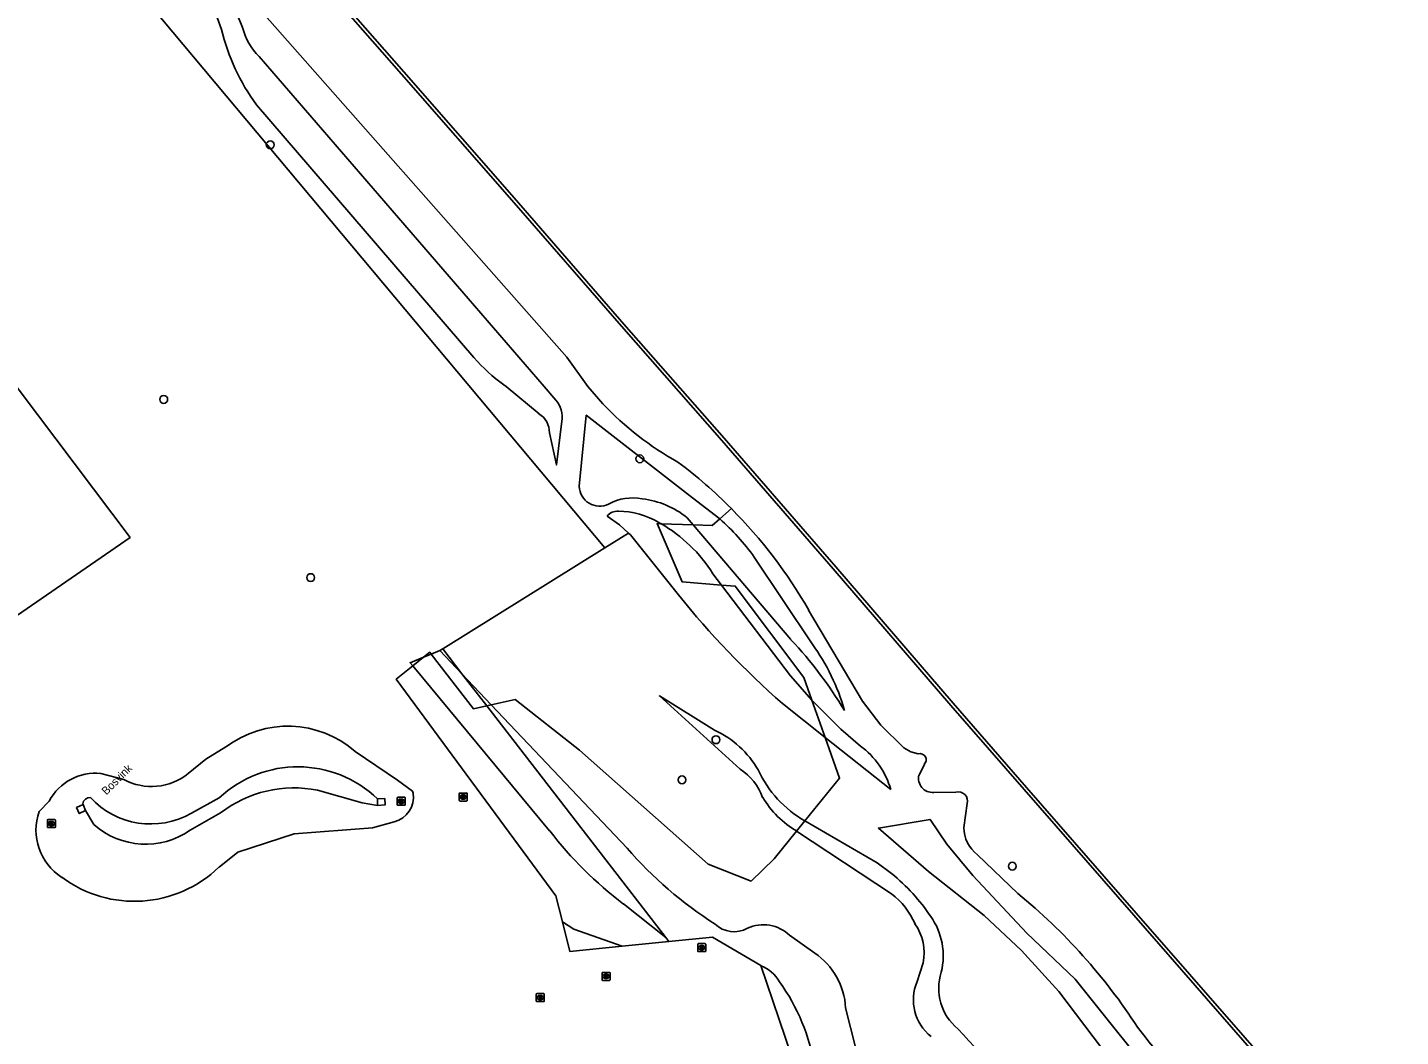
# Model space of a CAD drawing. Extents: x 156664 to 157568, y 383571 to 384421.
# Drawn here: x 157142.1 to 157313.7, y 383918.8 to 384044.9 of the extents above; entities that cross this region are included whole.
import ezdxf

# ---------------------------------------------------------------- set-up
doc = ezdxf.new("R2010")
doc.units = 0
for name, color, linetype in [('IMGEO_Boom', 7, 'Continuous'), ('IMGEO_Gemengd_bos', 7, 'Continuous'), ('IMGEO_Greppel_droge_sloot', 7, 'Continuous'), ('IMGEO_Groenvoorziening', 7, 'Continuous'), ('IMGEO_Hek', 7, 'Continuous'), ('IMGEO_Houtwal', 7, 'Continuous'), ('IMGEO_Kademuur', 7, 'Continuous'), ('IMGEO_Kolk', 7, 'Continuous'), ('IMGEO_Loofbos', 7, 'Continuous'), ('IMGEO_Openbare_ruimte_label', 7, 'Continuous'), ('IMGEO_Rioolput', 7, 'Continuous'), ('IMGEO_Terreindeel_gesloten', 7, 'Continuous')]:
    doc.layers.add(name, color=color, linetype=linetype)

msp = doc.modelspace()

# ---------------------------------------------------------------- linework, layer by layer
at = {"layer": 'IMGEO_Boom'}
for centre in [(157172.48, 384030.23), (157159.17, 383998.4), (157218.67, 383990.98), (157177.53, 383976.13), (157228.18, 383955.86), (157223.94, 383950.85), (157265.22, 383940.05)]:
    msp.add_circle(centre, 0.489, dxfattribs=at)
at = {"layer": 'IMGEO_Gemengd_bos'}
for points in [[(157228.65, 383983.48), (157230.11, 383984.75)], [(157221.29, 383982.87), (157225.32, 383982.73)], [(157239.77, 383972.07), (157246.51, 383960.69), (157248.79, 383957.68), (157251.67, 383954.83), (157252.53, 383954.36), (157253.47, 383954.09)], [(157238.27, 383944.43), (157235.47, 383940.96), (157232.58, 383938.19), (157227.2, 383940.31), (157211.14, 383954.54), (157203.08, 383960.87), (157200.11, 383960.22)], [(157228.01, 383957.05), (157221.12, 383961.34), (157231.2, 383952.19)], [(157240.17, 383960.81), (157243.8, 383957.17), (157246.25, 383955.07)], [(157200.11, 383960.22), (157199.53, 383960.09)], [(157200.11, 383960.22), (157217.09, 383942.31)], [(157239.3, 383945.71), (157243.63, 383951.07), (157241.83, 383956.14)], [(157250.03, 383949.63), (157241.83, 383956.14)], [(157254.23, 383952.79), (157253.56, 383951.45)], [(157255.41, 383949.28), (157258.18, 383949.3)], [(157259.59, 383947.9), (157259.15, 383944.9)], [(157239.3, 383945.71), (157238.27, 383944.43)], [(157250.14, 383939.13), (157248.32, 383940.46), (157239.3, 383945.71)], [(157303.47, 383891.7), (157300.02, 383895.94), (157297.8, 383897.29), (157289.36, 383906.54), (157284.6, 383911.52), (157273.07, 383925.95), (157267.04, 383931.67), (157260.3, 383938.88), (157257.03, 383942.79), (157254.94, 383945.91), (157248.49, 383944.82), (157254.75, 383939.38), (157261.69, 383933.87), (157266.36, 383929.5), (157271.02, 383924.41), (157276.36, 383917.34), (157282.3, 383910.19), (157297.68, 383894.11), (157299.46, 383892.07), (157301.69, 383888.84), (157300.48, 383888.07), (157303.25, 383884.02)], [(157250.13, 383936.61), (157238.27, 383944.43)], [(157260.86, 383941.47), (157265.93, 383936.62)], [(157222.29, 383930.64), (157227.77, 383931.19), (157233.78, 383927.62)], [(157237.39, 383931.42), (157240.53, 383929.17)], [(157253.32, 383925.62), (157254.09, 383927.96)], [(157244.39, 383922.35), (157245.62, 383917.45)]]:
    msp.add_lwpolyline(points, dxfattribs=at)
for centre, radius, start, end in [((157186.72, 383941.66), 61.15, 29.8152, 44.7984), ((157222.96, 383946.06), 12.1, 29.8538, 65.3154), ((157240.04, 383946.72), 10.41, 16.2761, 53.3333), ((157253.69, 383953.35), 0.772, 313.8246, 106.7158), ((157227.4, 383946.25), 7.04, 19.8803, 57.4196), ((157246.5, 383958.18), 14.4, 205.0583, 240.022), ((157255.24, 383951.01), 1.74, 165.4769, 275.4287), ((157244.62, 383955.06), 12.38, 211.1926, 239.1594), ((157258.49, 383948.2), 1.14, 344.5925, 106.0172), ((157263.58, 383944.97), 4.43, 180.8714, 232.1785), ((157254.93, 383975.03), 50.03, 220.8459, 237.5294), ((157235.24, 383920.64), 23.74, 33.5708, 51.1424), ((157243.79, 383928.62), 10.2, 24.5965, 51.576), ((157219.84, 383880.31), 72.77, 32.9958, 50.7037), ((157230.44, 383935.23), 3.37, 225.5364, 299.7246), ((157247.8, 383929.21), 6.4, 348.7541, 34.8077), ((157248, 383928.83), 8.59, 346.3576, 35.1112), ((157234.1, 383927.95), 4.78, 46.4665, 114.5596), ((157235.58, 383921.87), 8.82, 3.1419, 55.8635), ((157232.08, 383923.27), 4.67, 30.02, 68.5963), ((157262.53, 383924.79), 6.51, 161.9515, 230.875), ((157216.14, 383911.15), 24.66, 8.9825, 35.887), ((157258.75, 383923.35), 5.89, 157.3225, 231.3189), ((157303.08, 383959.04), 59.49, 221.3471, 237.1641), ((157379.75, 383994.77), 124, 217.1164, 228.5496)]:
    msp.add_arc(centre, radius, start, end, dxfattribs=at)
at = {"layer": 'IMGEO_Greppel_droge_sloot'}
for points in [[(157166.11, 383948.59), (157162.63, 383946.67)], [(157178.39, 383949.54), (157183.98, 383947.96), (157185.9, 383947.65), (157185.9, 383947.66)], [(157185.9, 383947.66), (157185.9, 383948.46)], [(157149.06, 383947.84), (157149.09, 383947.75)], [(157149.09, 383947.75), (157149.41, 383947.01)], [(157149.41, 383947.01), (157150.45, 383945.26)], [(157162.48, 383944.55), (157166.28, 383946.71)]]:
    msp.add_lwpolyline(points, dxfattribs=at)
for centre, radius, start, end in [((157175.93, 383938.12), 14.36, 46.057, 133.1961), ((157149.96, 383947.72), 0.913, 87.0362, 172.8465), ((157157.55, 383955.59), 10.26, 222.6552, 299.6813), ((157175.41, 383934.98), 14.86, 78.4476, 127.8989), ((157156.91, 383952.49), 9.69, 228.1896, 305.0149)]:
    msp.add_arc(centre, radius, start, end, dxfattribs=at)
at = {"layer": 'IMGEO_Groenvoorziening'}
for points in [[(157095.74, 384121.39), (157214.31, 383979.84)], [(157047.52, 384049.68), (157048.49, 384046.4), (157118.08, 383955.71), (157154.96, 383981.15), (157087.62, 384070.54), (157084.35, 384074.37)], [(157214.31, 383979.84), (157217.27, 383981.69)], [(157214.31, 383979.84), (157194.04, 383967.21)], [(157194.04, 383967.21), (157193.69, 383967)], [(157194.04, 383967.21), (157196.44, 383964.1)], [(157191.63, 383966.17), (157189.95, 383965.49), (157190.29, 383965.09)], [(157192.61, 383966.56), (157192.42, 383966.8), (157191.63, 383966.17)], [(157200.11, 383960.22), (157196.44, 383964.1)], [(157166.95, 383954.96), (157164.45, 383953.44), (157162.24, 383951.62)], [(157190.25, 383949.45), (157188.39, 383950.82), (157183.1, 383954.38)], [(157154.17, 383950.88), (157151.32, 383951.62)], [(157190.36, 383949.17), (157190.25, 383949.45)], [(157144.87, 383948.19), (157143.6, 383946.88)], [(157166.08, 383939.94), (157168.41, 383941.82), (157175.48, 383944.08), (157185.25, 383944.83), (157187.96, 383945.61)], [(157233.78, 383927.62), (157237.6, 383916.48), (157235.41, 383912.05)]]:
    msp.add_lwpolyline(points, dxfattribs=at)
for centre, radius, start, end in [((157174.67, 383944.78), 12.78, 48.7114, 127.1896), ((157150.62, 383945.16), 6.51, 83.8156, 152.216), ((157157.64, 383957.39), 7.37, 241.9236, 308.5702), ((157187.14, 383948.75), 3.25, 284.7009, 7.3932), ((157150.18, 383944.56), 6.98, 160.637, 237.6994), ((157155.51, 383950.82), 15.16, 233.2939, 314.1575)]:
    msp.add_arc(centre, radius, start, end, dxfattribs=at)
at = {"layer": 'IMGEO_Hek'}
for points in [[(157194.04, 383967.21), (157196.44, 383964.1)], [(157196.44, 383964.1), (157199.53, 383960.09)], [(157199.53, 383960.09), (157221.91, 383931.13)]]:
    msp.add_lwpolyline(points, dxfattribs=at)
at = {"layer": 'IMGEO_Houtwal'}
msp.add_lwpolyline([(157168.33, 384050.41), (157209.55, 384003.67), (157212.18, 384000), (157214.05, 383997.86)], dxfattribs=at)
for centre, radius, start, end in [((157242.19, 384024.36), 38.65, 223.2743, 240.9715), ((157186.7, 383941.66), 61.17, 44.7943, 53.0885)]:
    msp.add_arc(centre, radius, start, end, dxfattribs=at)
at = {"layer": 'IMGEO_Kademuur'}
for points in [[(157139.95, 384094.76), (157138.9, 384095.94), (157138.92, 384096.14), (157139.23, 384096.4), (157144.99, 384089.82), (157158.9, 384073.9), (157171.41, 384059.63), (157179.52, 384050.39), (157189.18, 384039.33), (157202.96, 384023.58), (157216.69, 384007.81), (157229.23, 383993.54), (157243.16, 383977.49), (157257.85, 383960.42), (157267.01, 383949.91), (157280.72, 383934.19), (157294.31, 383918.59), (157307.06, 383903.94), (157311.27, 383899.09), (157313.54, 383896.26), (157313.74, 383894.72)], [(157142.02, 384092.64), (157144.69, 384089.56), (157158.6, 384073.63), (157171.11, 384059.37), (157179.22, 384050.12), (157188.88, 384039.06), (157202.66, 384023.32), (157216.39, 384007.55), (157228.93, 383993.27), (157242.85, 383977.23), (157257.55, 383960.15), (157266.71, 383949.64), (157280.42, 383933.92), (157294.01, 383918.32), (157306.76, 383903.67), (157310.96, 383898.84), (157313.16, 383896.1), (157313.34, 383894.66), (157313.74, 383894.72)]]:
    msp.add_lwpolyline(points, dxfattribs=at)
at = {"layer": 'IMGEO_Kolk'}
for p, q in [((157188.35, 383947.75), (157188.35, 383948.6)), ((157188.43, 383948.67), (157189.28, 383948.67)), ((157188.84, 383948.45), (157188.87, 383948.45)), ((157189.36, 383948.6), (157189.36, 383947.75)), ((157189.28, 383947.67), (157188.43, 383947.67)), ((157188.86, 383947.89), (157188.84, 383947.89)), ((157144.63, 383944.95), (157144.63, 383945.81)), ((157144.7, 383945.88), (157145.56, 383945.88)), ((157145.56, 383944.88), (157144.7, 383944.88)), ((157145.14, 383945.1), (157145.11, 383945.1)), ((157145.12, 383945.66), (157145.14, 383945.66)), ((157145.63, 383945.81), (157145.63, 383944.95))]:
    msp.add_line(p, q, dxfattribs=at)
for points in [[(157188.35, 383947.75), (157188.35, 383948.6)], [(157188.43, 383948.67), (157189.28, 383948.67)], [(157188.67, 383948.37), (157188.8, 383948.37), (157188.8, 383948.22), (157188.93, 383948.37), (157189.09, 383948.37), (157188.95, 383948.22), (157189.1, 383947.97), (157188.95, 383947.97), (157188.86, 383948.14), (157188.8, 383948.07), (157188.8, 383947.97), (157188.67, 383947.97), (157188.67, 383948.37)], [(157189.36, 383948.6), (157189.36, 383947.75)], [(157189.28, 383947.67), (157188.43, 383947.67)], [(157144.63, 383944.95), (157144.63, 383945.81)], [(157144.7, 383945.88), (157145.56, 383945.88)], [(157145.56, 383944.88), (157144.7, 383944.88)], [(157144.95, 383945.58), (157145.07, 383945.58), (157145.07, 383945.43), (157145.2, 383945.58), (157145.37, 383945.58), (157145.22, 383945.43), (157145.37, 383945.18), (157145.22, 383945.18), (157145.14, 383945.34), (157145.07, 383945.28), (157145.07, 383945.18), (157144.95, 383945.18), (157144.95, 383945.58)], [(157145.63, 383945.81), (157145.63, 383944.95)]]:
    msp.add_lwpolyline(points, dxfattribs=at)
for centre, start, end in [((157188.43, 383948.6), 91.552, 178.448), ((157188.43, 383948.6), 91.552, 178.448), ((157189.28, 383948.6), 1.552, 88.448), ((157189.28, 383948.6), 1.552, 88.448), ((157188.43, 383947.75), 181.552, 268.448), ((157188.43, 383947.75), 181.552, 268.448), ((157189.28, 383947.75), 271.552, 358.448), ((157189.28, 383947.75), 271.552, 358.448), ((157144.71, 383945.8), 91.552, 178.448), ((157144.71, 383945.8), 91.552, 178.448), ((157144.71, 383944.96), 181.552, 268.448), ((157144.71, 383944.96), 181.552, 268.448), ((157145.55, 383945.8), 1.552, 88.448), ((157145.55, 383945.8), 1.552, 88.448), ((157145.55, 383944.96), 271.552, 358.448), ((157145.55, 383944.96), 271.552, 358.448)]:
    msp.add_arc(centre, 0.0765, start, end, dxfattribs=at)
for centre, major_axis, ratio, start_param, end_param in [((157188.84, 383948.17), (-0.387, 0.002), 0.722429, 4.712389, 7.853982), ((157188.87, 383948.17), (-0.39, 0.002), 0.717154, 1.570796, 4.712389), ((157145.12, 383945.38), (-0.387, 0.002), 0.722429, 4.712389, 7.853982), ((157145.14, 383945.38), (-0.39, 0.002), 0.717154, 1.570796, 4.712389)]:
    msp.add_ellipse(centre, major_axis=major_axis, ratio=ratio, start_param=start_param, end_param=end_param, dxfattribs=at)
at = {"layer": 'IMGEO_Loofbos'}
for points in [[(157165.83, 384046.13), (157166.38, 384044.65)], [(157207.93, 383998.59), (157206.71, 384000), (157171.09, 384041.26)], [(157170.76, 384035.22), (157197.94, 384003.63)], [(157201.69, 384000.22), (157201.95, 384000), (157206.07, 383996.62)], [(157228.65, 383983.48), (157225.25, 383986.11), (157211.98, 383996.42), (157211.09, 383987.54)], [(157207.38, 383994.23), (157208.25, 383990.21), (157208.98, 383996.03)], [(157217.27, 383981.69), (157216.11, 383982.74), (157214.58, 383983.82)], [(157221.29, 383982.87), (157220.82, 383982.89), (157223.95, 383975.6), (157228.87, 383975.2)], [(157221.05, 383983.01), (157221.29, 383982.87)], [(157224.58, 383983.6), (157225.32, 383982.73)], [(157228.65, 383983.48), (157227.69, 383982.65), (157225.32, 383982.73)], [(157225.32, 383982.73), (157237.55, 383968.37)], [(157223.51, 383973.96), (157217.49, 383981.49), (157217.27, 383981.69)], [(157240.19, 383967.83), (157232.97, 383978.7)], [(157228.87, 383975.2), (157227.81, 383976.61)], [(157240.17, 383960.81), (157239.17, 383963.64), (157230.59, 383975.07), (157228.87, 383975.2)], [(157228.87, 383975.2), (157237.49, 383963.85), (157240.17, 383960.81)], [(157191.63, 383966.17), (157190.29, 383965.09)], [(157192.61, 383966.56), (157191.63, 383966.17)], [(157193.69, 383967), (157192.61, 383966.56)], [(157199.53, 383960.09), (157197.87, 383959.73), (157192.61, 383966.56)], [(157196.44, 383964.1), (157193.69, 383967)], [(157190.29, 383965.09), (157188.23, 383963.43), (157208.19, 383936.36), (157209, 383933.11)], [(157190.29, 383965.09), (157207.4, 383944.48)], [(157199.53, 383960.09), (157196.44, 383964.1)], [(157241.83, 383956.14), (157236.51, 383960.37)], [(157240.17, 383960.81), (157241.83, 383956.14)], [(157221.91, 383931.13), (157199.53, 383960.09)], [(157216.63, 383935.33), (157221.91, 383931.13)], [(157209, 383933.11), (157210.42, 383932.17), (157216.46, 383930.05)], [(157209, 383933.11), (157209.92, 383929.4), (157216.46, 383930.05)], [(157222.29, 383930.64), (157221.91, 383931.13)], [(157216.46, 383930.05), (157222.29, 383930.64)]]:
    msp.add_lwpolyline(points, dxfattribs=at)
for centre, radius, start, end in [((157156.36, 384040.05), 13.56, 20.9435, 42.8742), ((157192.46, 384051.03), 26.85, 193.7387, 216.0861), ((157176.35, 384046.65), 7.53, 193.471, 225.7471), ((157215.25, 384018.85), 23.05, 221.3169, 233.9441), ((157205.64, 383996.15), 3.34, 357.8266, 46.8798), ((157204.65, 383994.29), 2.72, 358.6994, 58.7896), ((157213.66, 383987.63), 2.57, 182.2171, 295.5259), ((157217.73, 383980.04), 6.05, 78.1031, 119.3361), ((157215.86, 383982.77), 1.66, 85.5723, 140.7857), ((157215.89, 383974.32), 10.11, 59.3082, 89.4451), ((157217.78, 383975.27), 10.76, 50.7584, 83.5989), ((157212.06, 383966.75), 18.58, 32.052, 60.2073), ((157209.01, 383961.38), 29.56, 35.8481, 48.3681), ((157307.01, 384040.88), 107.01, 218.71, 228.7903), ((157199.79, 383932.87), 51.83, 30.923, 43.2254), ((157219.38, 383952.53), 25.83, 15.6766, 36.3184), ((157246.48, 383974.68), 49.39, 217.703, 232.8268)]:
    msp.add_arc(centre, radius, start, end, dxfattribs=at)
at = {"layer": 'IMGEO_Rioolput'}
for p, q in [((157196.09, 383948.28), (157196.09, 383949.13)), ((157196.17, 383949.2), (157197.02, 383949.2)), ((157196.58, 383948.98), (157196.61, 383948.98)), ((157196.6, 383948.42), (157196.58, 383948.42)), ((157197.09, 383949.13), (157197.09, 383948.28)), ((157197.02, 383948.2), (157196.17, 383948.2)), ((157225.9, 383929.44), (157225.9, 383930.29)), ((157225.98, 383930.37), (157226.83, 383930.37)), ((157226.83, 383929.37), (157225.98, 383929.37)), ((157226.39, 383930.15), (157226.42, 383930.15)), ((157226.41, 383929.59), (157226.39, 383929.59)), ((157226.9, 383930.29), (157226.9, 383929.44)), ((157213.95, 383925.85), (157213.95, 383926.7)), ((157214.03, 383926.78), (157214.88, 383926.78)), ((157214.44, 383926.56), (157214.47, 383926.56)), ((157214.46, 383926), (157214.44, 383926)), ((157214.95, 383926.7), (157214.95, 383925.85)), ((157214.88, 383925.78), (157214.03, 383925.78)), ((157205.73, 383923.2), (157205.73, 383924.06)), ((157205.81, 383924.13), (157206.66, 383924.13)), ((157206.66, 383923.13), (157205.81, 383923.13)), ((157206.22, 383923.91), (157206.24, 383923.91)), ((157206.24, 383923.35), (157206.22, 383923.35)), ((157206.73, 383924.06), (157206.73, 383923.2))]:
    msp.add_line(p, q, dxfattribs=at)
for points in [[(157196.09, 383948.28), (157196.09, 383949.13)], [(157196.17, 383949.2), (157197.02, 383949.2)], [(157196.68, 383948.9), (157196.43, 383948.9), (157196.43, 383948.5)], [(157196.43, 383948.5), (157196.55, 383948.5), (157196.55, 383948.67), (157196.57, 383948.67)], [(157196.61, 383948.82), (157196.55, 383948.82), (157196.55, 383948.74)], [(157196.55, 383948.74), (157196.61, 383948.74)], [(157196.61, 383948.64), (157196.68, 383948.5), (157196.82, 383948.5), (157196.76, 383948.63)], [(157197.09, 383949.13), (157197.09, 383948.28)], [(157197.02, 383948.2), (157196.17, 383948.2)], [(157225.9, 383929.44), (157225.9, 383930.29)], [(157225.98, 383930.37), (157226.83, 383930.37)], [(157226.83, 383929.37), (157225.98, 383929.37)], [(157226.49, 383930.06), (157226.24, 383930.07), (157226.24, 383929.67)], [(157226.24, 383929.67), (157226.36, 383929.67), (157226.36, 383929.83), (157226.37, 383929.83)], [(157226.42, 383929.99), (157226.36, 383929.99), (157226.36, 383929.9)], [(157226.36, 383929.9), (157226.41, 383929.9)], [(157226.42, 383929.8), (157226.49, 383929.67), (157226.63, 383929.67), (157226.57, 383929.79)], [(157226.9, 383930.29), (157226.9, 383929.44)], [(157213.95, 383925.85), (157213.95, 383926.7)], [(157214.03, 383926.78), (157214.88, 383926.78)], [(157214.54, 383926.48), (157214.29, 383926.48), (157214.29, 383926.08)], [(157214.29, 383926.08), (157214.41, 383926.08), (157214.41, 383926.24), (157214.42, 383926.24)], [(157214.47, 383926.4), (157214.41, 383926.4), (157214.41, 383926.32)], [(157214.41, 383926.32), (157214.46, 383926.32)], [(157214.47, 383926.21), (157214.54, 383926.08), (157214.68, 383926.08), (157214.62, 383926.2)], [(157214.95, 383926.7), (157214.95, 383925.85)], [(157214.88, 383925.78), (157214.03, 383925.78)], [(157205.73, 383923.2), (157205.73, 383924.06)], [(157205.81, 383924.13), (157206.66, 383924.13)], [(157206.66, 383923.13), (157205.81, 383923.13)], [(157206.32, 383923.83), (157206.07, 383923.83), (157206.07, 383923.43)], [(157206.07, 383923.43), (157206.19, 383923.43), (157206.19, 383923.59), (157206.2, 383923.59)], [(157206.25, 383923.75), (157206.19, 383923.75), (157206.19, 383923.67)], [(157206.19, 383923.67), (157206.24, 383923.67)], [(157206.25, 383923.56), (157206.32, 383923.43), (157206.46, 383923.43), (157206.4, 383923.56)], [(157206.73, 383924.06), (157206.73, 383923.2)]]:
    msp.add_lwpolyline(points, dxfattribs=at)
for centre, radius, start, end in [((157196.17, 383949.13), 0.0765, 91.552, 178.448), ((157196.17, 383949.13), 0.0765, 91.552, 178.448), ((157196.17, 383948.28), 0.0765, 181.552, 268.448), ((157196.17, 383948.28), 0.0765, 181.552, 268.448), ((157196.56, 383948.61), 0.0533, 26.0293, 88.6989), ((157196.61, 383948.73), 0.0964, 77.0061, 93.1865), ((157196.59, 383948.93), 0.19, 274.7715, 282.9687), ((157196.63, 383948.78), 0.0378, 276.6634, 79.6772), ((157196.68, 383948.79), 0.109, 350.3612, 89.416), ((157196.68, 383948.79), 0.112, 277.5842, 350.9817), ((157196.66, 383948.58), 0.108, 29.5134, 73.7905), ((157197.02, 383949.13), 0.0765, 1.552, 88.448), ((157197.02, 383949.13), 0.0765, 1.552, 88.448), ((157197.02, 383948.28), 0.0765, 271.552, 358.448), ((157197.02, 383948.28), 0.0765, 271.552, 358.448), ((157225.98, 383930.29), 0.0765, 91.552, 178.448), ((157225.98, 383930.29), 0.0765, 91.552, 178.448), ((157225.98, 383929.44), 0.0765, 181.552, 268.448), ((157225.98, 383929.44), 0.0765, 181.552, 268.448), ((157226.37, 383929.78), 0.0533, 26.0293, 88.6989), ((157226.4, 383930.09), 0.19, 274.7715, 282.9687), ((157226.42, 383929.89), 0.0964, 77.0061, 93.1865), ((157226.44, 383929.95), 0.0378, 276.6634, 79.6772), ((157226.49, 383929.95), 0.109, 350.3612, 89.416), ((157226.49, 383929.95), 0.112, 277.5842, 350.9817), ((157226.47, 383929.74), 0.108, 29.5134, 73.7905), ((157226.83, 383930.29), 0.0765, 1.552, 88.448), ((157226.83, 383930.29), 0.0765, 1.552, 88.448), ((157226.83, 383929.44), 0.0765, 271.552, 358.448), ((157226.83, 383929.44), 0.0765, 271.552, 358.448), ((157214.03, 383926.7), 0.0765, 91.552, 178.448), ((157214.03, 383926.7), 0.0765, 91.552, 178.448), ((157214.42, 383926.19), 0.0533, 26.0293, 88.6989), ((157214.45, 383926.51), 0.19, 274.7715, 282.9687), ((157214.47, 383926.3), 0.0964, 77.0061, 93.1865), ((157214.49, 383926.36), 0.0378, 276.6634, 79.6772), ((157214.54, 383926.37), 0.109, 350.3612, 89.416), ((157214.54, 383926.37), 0.112, 277.5842, 350.9817), ((157214.52, 383926.15), 0.108, 29.5134, 73.7905), ((157214.88, 383926.7), 0.0765, 1.552, 88.448), ((157214.88, 383926.7), 0.0765, 1.552, 88.448), ((157214.03, 383925.85), 0.0765, 181.552, 268.448), ((157214.03, 383925.85), 0.0765, 181.552, 268.448), ((157214.88, 383925.85), 0.0765, 271.552, 358.448), ((157214.88, 383925.85), 0.0765, 271.552, 358.448), ((157205.81, 383924.05), 0.0765, 91.552, 178.448), ((157205.81, 383924.05), 0.0765, 91.552, 178.448), ((157205.81, 383923.2), 0.0765, 181.552, 268.448), ((157205.81, 383923.2), 0.0765, 181.552, 268.448), ((157206.2, 383923.54), 0.0533, 26.0293, 88.6989), ((157206.23, 383923.86), 0.19, 274.7715, 282.9687), ((157206.25, 383923.65), 0.0964, 77.0061, 93.1865), ((157206.27, 383923.71), 0.0378, 276.6634, 79.6772), ((157206.32, 383923.72), 0.109, 350.3612, 89.416), ((157206.32, 383923.72), 0.112, 277.5842, 350.9817), ((157206.3, 383923.5), 0.108, 29.5134, 73.7905), ((157206.66, 383924.05), 0.0765, 1.552, 88.448), ((157206.66, 383924.05), 0.0765, 1.552, 88.448), ((157206.66, 383923.2), 0.0765, 271.552, 358.448), ((157206.66, 383923.2), 0.0765, 271.552, 358.448)]:
    msp.add_arc(centre, radius, start, end, dxfattribs=at)
for centre, major_axis, ratio, start_param, end_param in [((157196.58, 383948.7), (-0.387, 0.002), 0.722429, 4.712389, 7.853982), ((157196.6, 383948.7), (-0.39, 0.002), 0.717154, 1.570796, 4.712389), ((157226.39, 383929.87), (-0.387, 0.002), 0.722429, 4.712389, 7.853982), ((157226.41, 383929.87), (-0.39, 0.002), 0.717154, 1.570796, 4.712389), ((157214.44, 383926.28), (-0.387, 0.002), 0.722429, 4.712389, 7.853982), ((157214.46, 383926.28), (-0.39, 0.002), 0.717154, 1.570796, 4.712389), ((157206.22, 383923.63), (-0.387, 0.002), 0.722429, 4.712389, 7.853982), ((157206.24, 383923.63), (-0.39, 0.002), 0.717154, 1.570796, 4.712389)]:
    msp.add_ellipse(centre, major_axis=major_axis, ratio=ratio, start_param=start_param, end_param=end_param, dxfattribs=at)
at = {"layer": 'IMGEO_Terreindeel_gesloten'}
for points in [[(157185.9, 383948.46), (157186.8, 383948.51), (157186.84, 383947.72), (157185.9, 383947.66)], [(157149.09, 383947.75), (157148.27, 383947.37), (157148.61, 383946.63), (157149.41, 383947.01)]]:
    msp.add_lwpolyline(points, dxfattribs=at)

# ---------------------------------------------------------------- texts
at = {"layer": 'IMGEO_Openbare_ruimte_label'}
msp.add_text('Bosvink', height=1, rotation=45, dxfattribs=at).set_placement((157152, 383948.88))

doc.saveas('drawing.dxf')
